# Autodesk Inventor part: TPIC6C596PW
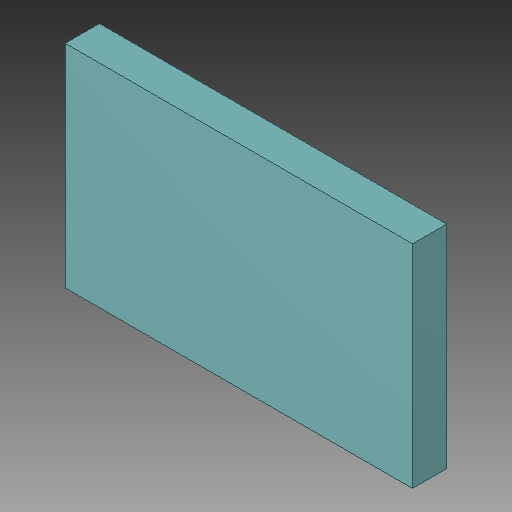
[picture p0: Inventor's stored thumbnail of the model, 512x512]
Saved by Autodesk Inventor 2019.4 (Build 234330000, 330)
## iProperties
Created: 2019-11
Part Number: TPIC6C596PW
Material: Generic
Document SubType Name: Modeling
Designer: Willist
Density: 1 g/cm^3
Appearance: SO16, TPIC6C596PW
Author: Willist
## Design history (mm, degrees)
sketch "SO16, TPIC6C596PW_66"
  geometry: L1 (-5.08, 3.099)-(5.08, 3.099); L2 (5.08, 3.099)-(5.08, -3.099); L3 (5.08, -3.099)-(-5.08, -3.099); L4 (-5.08, -3.099)-(-5.08, 3.099)
  constraints: 8 end point
extrude "Extrusion1" join sketch "SO16, TPIC6C596PW_66" distance "d0" = 1; taper "d1" = 0 deg
body "Solid1"
